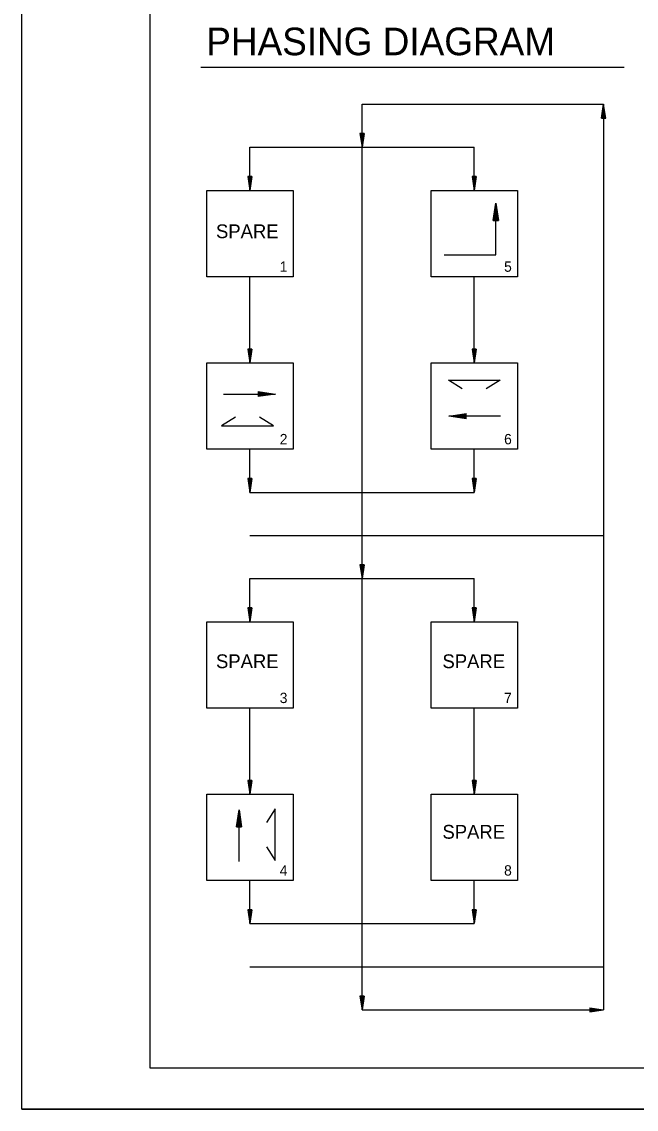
# Model space of a CAD drawing. Extents: x 1280742 to 1281742, y 1892348 to 1892988.
# Drawn here: x 1280741.9 to 1280919.9, y 1892348 to 1892663.2 of the extents above; entities that cross this region are included whole.
import ezdxf

# ---------------------------------------------------------------- set-up
doc = ezdxf.new("R2010")
doc.units = 0
for name, color, linetype in [('R_Border', 7, 'Continuous'), ('R_Draft', 7, 'Continuous'), ('R_No Plot', 7, 'Continuous'), ('T_Drafting', 7, 'Continuous'), ('T_Notes', 7, 'Continuous')]:
    doc.layers.add(name, color=color, linetype=linetype)

msp = doc.modelspace()

# ---------------------------------------------------------------- linework, layer by layer
at = {"layer": 'R_Border'}
for p, q in [((1280779.11, 1892359.96), (1280779.11, 1892976.34)), ((1280779.11, 1892359.96), (1280779.11, 1892575.44)), ((1281154.16, 1892359.96), (1280779.11, 1892359.96)), ((1280779.11, 1892359.96), (1280779.11, 1892359.96)), ((1281727.65, 1892359.96), (1280779.11, 1892359.96))]:
    msp.add_line(p, q, dxfattribs=at)
at = {"layer": 'R_Draft'}
for p, q in [((1280909.87, 1892635.3), (1280910.47, 1892639.3)), ((1280909.97, 1892635.3), (1280910.47, 1892638.64)), ((1280910.07, 1892635.3), (1280910.47, 1892637.95)), ((1280910.17, 1892635.3), (1280910.47, 1892637.28)), ((1280911.07, 1892635.3), (1280910.47, 1892639.3)), ((1280910.97, 1892635.3), (1280910.47, 1892638.64)), ((1280910.87, 1892635.3), (1280910.47, 1892637.95)), ((1280910.77, 1892635.3), (1280910.47, 1892637.28)), ((1280909.87, 1892635.3), (1280911.07, 1892635.3)), ((1280910.28, 1892635.3), (1280910.47, 1892636.6)), ((1280910.38, 1892635.3), (1280910.47, 1892635.94)), ((1280910.67, 1892635.3), (1280910.47, 1892636.6)), ((1280910.56, 1892635.3), (1280910.47, 1892635.94)), ((1280839.87, 1892630.8), (1280840.47, 1892626.8)), ((1280841.07, 1892630.8), (1280839.87, 1892630.8)), ((1280839.97, 1892630.8), (1280840.47, 1892627.47)), ((1280840.07, 1892630.8), (1280840.47, 1892628.16)), ((1280840.17, 1892630.8), (1280840.47, 1892628.83)), ((1280840.27, 1892630.8), (1280840.47, 1892629.5)), ((1280840.38, 1892630.8), (1280840.47, 1892630.17)), ((1280841.07, 1892630.8), (1280840.47, 1892626.8)), ((1280840.66, 1892630.8), (1280840.47, 1892629.5)), ((1280840.87, 1892630.8), (1280840.47, 1892628.16)), ((1280840.97, 1892630.8), (1280840.47, 1892627.47)), ((1280840.77, 1892630.8), (1280840.47, 1892628.83)), ((1280840.56, 1892630.8), (1280840.47, 1892630.17)), ((1280807.37, 1892618.3), (1280807.97, 1892614.3)), ((1280808.57, 1892618.3), (1280807.37, 1892618.3)), ((1280807.47, 1892618.3), (1280807.97, 1892614.97)), ((1280807.57, 1892618.3), (1280807.97, 1892615.66)), ((1280807.67, 1892618.3), (1280807.97, 1892616.33)), ((1280807.77, 1892618.3), (1280807.97, 1892617)), ((1280807.88, 1892618.3), (1280807.97, 1892617.67)), ((1280808.57, 1892618.3), (1280807.97, 1892614.3)), ((1280808.16, 1892618.3), (1280807.97, 1892617)), ((1280808.37, 1892618.3), (1280807.97, 1892615.66)), ((1280808.47, 1892618.3), (1280807.97, 1892614.97)), ((1280808.27, 1892618.3), (1280807.97, 1892616.33)), ((1280808.06, 1892618.3), (1280807.97, 1892617.67)), ((1280872.37, 1892618.3), (1280872.97, 1892614.3)), ((1280873.57, 1892618.3), (1280872.37, 1892618.3)), ((1280872.47, 1892618.3), (1280872.97, 1892614.97)), ((1280872.57, 1892618.3), (1280872.97, 1892615.66)), ((1280872.67, 1892618.3), (1280872.97, 1892616.33)), ((1280872.77, 1892618.3), (1280872.97, 1892617)), ((1280872.88, 1892618.3), (1280872.97, 1892617.67)), ((1280873.57, 1892618.3), (1280872.97, 1892614.3)), ((1280873.16, 1892618.3), (1280872.97, 1892617)), ((1280873.37, 1892618.3), (1280872.97, 1892615.66)), ((1280873.47, 1892618.3), (1280872.97, 1892614.97)), ((1280873.27, 1892618.3), (1280872.97, 1892616.33)), ((1280873.06, 1892618.3), (1280872.97, 1892617.67)), ((1280807.37, 1892568.3), (1280807.97, 1892564.3)), ((1280808.57, 1892568.3), (1280807.37, 1892568.3)), ((1280807.47, 1892568.3), (1280807.97, 1892564.97)), ((1280807.57, 1892568.3), (1280807.97, 1892565.66)), ((1280807.67, 1892568.3), (1280807.97, 1892566.33)), ((1280807.77, 1892568.3), (1280807.97, 1892567)), ((1280807.88, 1892568.3), (1280807.97, 1892567.67)), ((1280808.57, 1892568.3), (1280807.97, 1892564.3)), ((1280808.16, 1892568.3), (1280807.97, 1892567)), ((1280808.37, 1892568.3), (1280807.97, 1892565.66)), ((1280808.47, 1892568.3), (1280807.97, 1892564.97)), ((1280808.27, 1892568.3), (1280807.97, 1892566.33)), ((1280808.06, 1892568.3), (1280807.97, 1892567.67)), ((1280872.37, 1892568.3), (1280872.97, 1892564.3)), ((1280873.57, 1892568.3), (1280872.37, 1892568.3)), ((1280872.47, 1892568.3), (1280872.97, 1892564.97)), ((1280872.57, 1892568.3), (1280872.97, 1892565.66)), ((1280872.67, 1892568.3), (1280872.97, 1892566.33)), ((1280872.77, 1892568.3), (1280872.97, 1892567)), ((1280872.88, 1892568.3), (1280872.97, 1892567.67)), ((1280873.57, 1892568.3), (1280872.97, 1892564.3)), ((1280873.16, 1892568.3), (1280872.97, 1892567)), ((1280873.37, 1892568.3), (1280872.97, 1892565.66)), ((1280873.47, 1892568.3), (1280872.97, 1892564.97)), ((1280873.27, 1892568.3), (1280872.97, 1892566.33)), ((1280873.06, 1892568.3), (1280872.97, 1892567.67)), ((1280807.37, 1892530.8), (1280807.97, 1892526.8)), ((1280808.57, 1892530.8), (1280807.37, 1892530.8)), ((1280807.47, 1892530.8), (1280807.97, 1892527.47)), ((1280807.57, 1892530.8), (1280807.97, 1892528.16)), ((1280807.67, 1892530.8), (1280807.97, 1892528.83)), ((1280807.77, 1892530.8), (1280807.97, 1892529.5)), ((1280807.88, 1892530.8), (1280807.97, 1892530.17)), ((1280808.57, 1892530.8), (1280807.97, 1892526.8)), ((1280808.16, 1892530.8), (1280807.97, 1892529.5)), ((1280808.37, 1892530.8), (1280807.97, 1892528.16)), ((1280808.47, 1892530.8), (1280807.97, 1892527.47)), ((1280808.27, 1892530.8), (1280807.97, 1892528.83)), ((1280808.06, 1892530.8), (1280807.97, 1892530.17)), ((1280872.37, 1892530.8), (1280872.97, 1892526.8)), ((1280873.57, 1892530.8), (1280872.37, 1892530.8)), ((1280872.47, 1892530.8), (1280872.97, 1892527.47)), ((1280872.57, 1892530.8), (1280872.97, 1892528.16)), ((1280872.67, 1892530.8), (1280872.97, 1892528.83)), ((1280872.77, 1892530.8), (1280872.97, 1892529.5)), ((1280872.88, 1892530.8), (1280872.97, 1892530.17)), ((1280873.57, 1892530.8), (1280872.97, 1892526.8)), ((1280873.16, 1892530.8), (1280872.97, 1892529.5)), ((1280873.37, 1892530.8), (1280872.97, 1892528.16)), ((1280873.47, 1892530.8), (1280872.97, 1892527.47)), ((1280873.27, 1892530.8), (1280872.97, 1892528.83)), ((1280873.06, 1892530.8), (1280872.97, 1892530.17)), ((1280839.87, 1892505.8), (1280840.47, 1892501.8)), ((1280841.07, 1892505.8), (1280839.87, 1892505.8)), ((1280839.97, 1892505.8), (1280840.47, 1892502.47)), ((1280840.07, 1892505.8), (1280840.47, 1892503.16)), ((1280840.17, 1892505.8), (1280840.47, 1892503.83)), ((1280840.27, 1892505.8), (1280840.47, 1892504.5)), ((1280840.38, 1892505.8), (1280840.47, 1892505.17)), ((1280841.07, 1892505.8), (1280840.47, 1892501.8)), ((1280840.66, 1892505.8), (1280840.47, 1892504.5)), ((1280840.87, 1892505.8), (1280840.47, 1892503.16)), ((1280840.97, 1892505.8), (1280840.47, 1892502.47)), ((1280840.77, 1892505.8), (1280840.47, 1892503.83)), ((1280840.56, 1892505.8), (1280840.47, 1892505.17)), ((1280807.37, 1892493.3), (1280807.97, 1892489.3)), ((1280808.57, 1892493.3), (1280807.37, 1892493.3)), ((1280807.47, 1892493.3), (1280807.97, 1892489.97)), ((1280807.57, 1892493.3), (1280807.97, 1892490.66)), ((1280807.67, 1892493.3), (1280807.97, 1892491.33)), ((1280807.77, 1892493.3), (1280807.97, 1892492)), ((1280807.88, 1892493.3), (1280807.97, 1892492.67)), ((1280808.57, 1892493.3), (1280807.97, 1892489.3)), ((1280808.16, 1892493.3), (1280807.97, 1892492)), ((1280808.37, 1892493.3), (1280807.97, 1892490.66)), ((1280808.47, 1892493.3), (1280807.97, 1892489.97)), ((1280808.27, 1892493.3), (1280807.97, 1892491.33)), ((1280808.06, 1892493.3), (1280807.97, 1892492.67)), ((1280872.37, 1892493.3), (1280872.97, 1892489.3)), ((1280873.57, 1892493.3), (1280872.37, 1892493.3)), ((1280872.47, 1892493.3), (1280872.97, 1892489.97)), ((1280872.57, 1892493.3), (1280872.97, 1892490.66)), ((1280872.67, 1892493.3), (1280872.97, 1892491.33)), ((1280872.77, 1892493.3), (1280872.97, 1892492)), ((1280872.88, 1892493.3), (1280872.97, 1892492.67)), ((1280873.57, 1892493.3), (1280872.97, 1892489.3)), ((1280873.16, 1892493.3), (1280872.97, 1892492)), ((1280873.37, 1892493.3), (1280872.97, 1892490.66)), ((1280873.47, 1892493.3), (1280872.97, 1892489.97)), ((1280873.27, 1892493.3), (1280872.97, 1892491.33)), ((1280873.06, 1892493.3), (1280872.97, 1892492.67)), ((1280807.37, 1892443.3), (1280807.97, 1892439.3)), ((1280808.57, 1892443.3), (1280807.37, 1892443.3)), ((1280807.47, 1892443.3), (1280807.97, 1892439.97)), ((1280807.57, 1892443.3), (1280807.97, 1892440.66)), ((1280807.67, 1892443.3), (1280807.97, 1892441.33)), ((1280807.77, 1892443.3), (1280807.97, 1892442)), ((1280807.88, 1892443.3), (1280807.97, 1892442.67)), ((1280808.57, 1892443.3), (1280807.97, 1892439.3)), ((1280808.16, 1892443.3), (1280807.97, 1892442)), ((1280808.37, 1892443.3), (1280807.97, 1892440.66)), ((1280808.47, 1892443.3), (1280807.97, 1892439.97)), ((1280808.27, 1892443.3), (1280807.97, 1892441.33)), ((1280808.06, 1892443.3), (1280807.97, 1892442.67)), ((1280872.37, 1892443.3), (1280872.97, 1892439.3)), ((1280873.57, 1892443.3), (1280872.37, 1892443.3)), ((1280872.47, 1892443.3), (1280872.97, 1892439.97)), ((1280872.57, 1892443.3), (1280872.97, 1892440.66)), ((1280872.67, 1892443.3), (1280872.97, 1892441.33)), ((1280872.77, 1892443.3), (1280872.97, 1892442)), ((1280872.88, 1892443.3), (1280872.97, 1892442.67)), ((1280873.57, 1892443.3), (1280872.97, 1892439.3)), ((1280873.16, 1892443.3), (1280872.97, 1892442)), ((1280873.37, 1892443.3), (1280872.97, 1892440.66)), ((1280873.47, 1892443.3), (1280872.97, 1892439.97)), ((1280873.27, 1892443.3), (1280872.97, 1892441.33)), ((1280873.06, 1892443.3), (1280872.97, 1892442.67)), ((1280807.37, 1892405.8), (1280807.97, 1892401.8)), ((1280808.57, 1892405.8), (1280807.37, 1892405.8)), ((1280807.47, 1892405.8), (1280807.97, 1892402.47)), ((1280807.57, 1892405.8), (1280807.97, 1892403.16)), ((1280807.67, 1892405.8), (1280807.97, 1892403.83)), ((1280807.77, 1892405.8), (1280807.97, 1892404.5)), ((1280807.88, 1892405.8), (1280807.97, 1892405.17)), ((1280808.57, 1892405.8), (1280807.97, 1892401.8)), ((1280808.16, 1892405.8), (1280807.97, 1892404.5)), ((1280808.37, 1892405.8), (1280807.97, 1892403.16)), ((1280808.47, 1892405.8), (1280807.97, 1892402.47)), ((1280808.27, 1892405.8), (1280807.97, 1892403.83)), ((1280808.06, 1892405.8), (1280807.97, 1892405.17)), ((1280872.37, 1892405.8), (1280872.97, 1892401.8)), ((1280873.57, 1892405.8), (1280872.37, 1892405.8)), ((1280872.47, 1892405.8), (1280872.97, 1892402.47)), ((1280872.57, 1892405.8), (1280872.97, 1892403.16)), ((1280872.67, 1892405.8), (1280872.97, 1892403.83)), ((1280872.77, 1892405.8), (1280872.97, 1892404.5)), ((1280872.88, 1892405.8), (1280872.97, 1892405.17)), ((1280873.57, 1892405.8), (1280872.97, 1892401.8)), ((1280873.16, 1892405.8), (1280872.97, 1892404.5)), ((1280873.37, 1892405.8), (1280872.97, 1892403.16)), ((1280873.47, 1892405.8), (1280872.97, 1892402.47)), ((1280873.27, 1892405.8), (1280872.97, 1892403.83)), ((1280873.06, 1892405.8), (1280872.97, 1892405.17)), ((1280839.87, 1892380.8), (1280840.47, 1892376.8)), ((1280841.07, 1892380.8), (1280839.87, 1892380.8)), ((1280839.97, 1892380.8), (1280840.47, 1892377.47)), ((1280840.07, 1892380.8), (1280840.47, 1892378.16)), ((1280840.17, 1892380.8), (1280840.47, 1892378.83)), ((1280840.27, 1892380.8), (1280840.47, 1892379.5)), ((1280840.38, 1892380.8), (1280840.47, 1892380.17)), ((1280841.07, 1892380.8), (1280840.47, 1892376.8)), ((1280840.66, 1892380.8), (1280840.47, 1892379.5)), ((1280840.87, 1892380.8), (1280840.47, 1892378.16)), ((1280840.97, 1892380.8), (1280840.47, 1892377.47)), ((1280840.77, 1892380.8), (1280840.47, 1892378.83)), ((1280840.56, 1892380.8), (1280840.47, 1892380.17)), ((1280906.47, 1892377.4), (1280910.47, 1892376.8)), ((1280906.47, 1892377.4), (1280906.47, 1892376.2)), ((1280906.47, 1892377.3), (1280909.8, 1892376.8)), ((1280906.47, 1892377.2), (1280909.11, 1892376.8)), ((1280906.47, 1892377.1), (1280908.45, 1892376.8)), ((1280906.47, 1892377), (1280907.77, 1892376.8)), ((1280906.47, 1892376.9), (1280907.1, 1892376.8)), ((1280906.47, 1892376.2), (1280910.47, 1892376.8)), ((1280906.47, 1892376.61), (1280907.77, 1892376.8)), ((1280906.47, 1892376.41), (1280909.11, 1892376.8)), ((1280906.47, 1892376.3), (1280909.8, 1892376.8)), ((1280906.47, 1892376.51), (1280908.45, 1892376.8)), ((1280906.47, 1892376.71), (1280907.1, 1892376.8))]:
    msp.add_line(p, q, dxfattribs=at)
at = {"layer": 'R_No Plot'}
msp.add_line((1280741.9, 1892348.02), (1281741.9, 1892348.02), dxfattribs=at)
msp.add_lwpolyline([(1280741.88, 1892988.02), (1281741.9, 1892988.02), (1281741.9, 1892348.01), (1280741.88, 1892348.01)], close=True, dxfattribs=at)
at = {"layer": 'T_Drafting'}
for p, q in [((1280840.47, 1892376.8), (1280840.47, 1892639.3)), ((1280840.47, 1892639.3), (1280910.47, 1892639.3)), ((1280910.47, 1892639.3), (1280910.47, 1892376.8)), ((1280807.97, 1892614.3), (1280807.97, 1892626.8)), ((1280807.97, 1892626.8), (1280872.97, 1892626.8)), ((1280872.97, 1892614.3), (1280872.97, 1892626.8)), ((1280878.47, 1892605.61), (1280879.22, 1892610.61)), ((1280879.22, 1892609.78), (1280878.6, 1892605.61)), ((1280878.73, 1892605.61), (1280879.22, 1892608.92)), ((1280879.22, 1892595.61), (1280879.22, 1892610.61)), ((1280879.22, 1892610.61), (1280879.97, 1892605.61)), ((1280879.85, 1892605.61), (1280879.22, 1892609.78)), ((1280879.22, 1892608.92), (1280879.72, 1892605.61)), ((1280878.47, 1892605.61), (1280879.97, 1892605.61)), ((1280879.22, 1892608.08), (1280878.85, 1892605.61)), ((1280878.98, 1892605.61), (1280879.22, 1892607.24)), ((1280879.22, 1892606.4), (1280879.11, 1892605.61)), ((1280879.6, 1892605.61), (1280879.22, 1892608.08)), ((1280879.22, 1892607.24), (1280879.47, 1892605.61)), ((1280879.34, 1892605.61), (1280879.22, 1892606.4)), ((1280864.22, 1892595.61), (1280879.22, 1892595.61)), ((1280807.97, 1892564.3), (1280807.97, 1892589.3)), ((1280872.97, 1892564.3), (1280872.97, 1892589.3)), ((1280800.37, 1892555.29), (1280815.37, 1892555.29)), ((1280810.37, 1892556.04), (1280815.37, 1892555.29)), ((1280810.37, 1892556.04), (1280810.37, 1892554.54)), ((1280814.53, 1892555.29), (1280810.37, 1892555.91)), ((1280810.37, 1892555.78), (1280813.67, 1892555.29)), ((1280812.84, 1892555.29), (1280810.37, 1892555.66)), ((1280810.37, 1892555.53), (1280811.99, 1892555.29)), ((1280811.16, 1892555.29), (1280810.37, 1892555.4)), ((1280815.37, 1892555.29), (1280810.37, 1892554.54)), ((1280810.37, 1892554.66), (1280814.53, 1892555.29)), ((1280813.67, 1892555.29), (1280810.37, 1892554.79)), ((1280810.37, 1892554.91), (1280812.84, 1892555.29)), ((1280811.99, 1892555.29), (1280810.37, 1892555.04)), ((1280810.37, 1892555.17), (1280811.16, 1892555.29)), ((1280865.61, 1892548.9), (1280870.61, 1892549.65)), ((1280880.61, 1892548.9), (1280865.61, 1892548.9)), ((1280870.61, 1892548.15), (1280865.61, 1892548.9)), ((1280870.61, 1892549.52), (1280866.44, 1892548.9)), ((1280866.44, 1892548.9), (1280870.61, 1892548.27)), ((1280867.3, 1892548.9), (1280870.61, 1892549.4)), ((1280870.61, 1892548.4), (1280867.3, 1892548.9)), ((1280870.61, 1892549.27), (1280868.13, 1892548.9)), ((1280868.13, 1892548.9), (1280870.61, 1892548.53)), ((1280868.98, 1892548.9), (1280870.61, 1892549.14)), ((1280870.61, 1892548.66), (1280868.98, 1892548.9)), ((1280870.61, 1892549.02), (1280869.82, 1892548.9)), ((1280869.82, 1892548.9), (1280870.61, 1892548.78)), ((1280870.61, 1892548.15), (1280870.61, 1892549.65)), ((1280807.97, 1892526.8), (1280807.97, 1892539.3)), ((1280872.97, 1892526.8), (1280872.97, 1892539.3)), ((1280807.97, 1892526.8), (1280872.97, 1892526.8)), ((1280807.97, 1892514.3), (1280910.47, 1892514.3)), ((1280807.97, 1892501.8), (1280872.97, 1892501.8)), ((1280807.97, 1892489.3), (1280807.97, 1892501.8)), ((1280872.97, 1892489.3), (1280872.97, 1892501.8)), ((1280807.97, 1892439.3), (1280807.97, 1892464.3)), ((1280872.97, 1892439.3), (1280872.97, 1892464.3)), ((1280804.09, 1892429.82), (1280804.84, 1892434.82)), ((1280804.84, 1892433.98), (1280804.22, 1892429.82)), ((1280804.34, 1892429.82), (1280804.84, 1892433.12)), ((1280804.84, 1892432.29), (1280804.47, 1892429.82)), ((1280804.84, 1892419.82), (1280804.84, 1892434.82)), ((1280804.84, 1892434.82), (1280805.59, 1892429.82)), ((1280805.47, 1892429.82), (1280804.84, 1892433.98)), ((1280804.84, 1892433.12), (1280805.34, 1892429.82)), ((1280805.21, 1892429.82), (1280804.84, 1892432.29)), ((1280804.09, 1892429.82), (1280805.59, 1892429.82)), ((1280804.6, 1892429.82), (1280804.84, 1892431.44)), ((1280804.84, 1892430.61), (1280804.72, 1892429.82)), ((1280804.84, 1892431.44), (1280805.09, 1892429.82)), ((1280804.96, 1892429.82), (1280804.84, 1892430.61)), ((1280807.97, 1892401.8), (1280807.97, 1892414.3)), ((1280872.97, 1892401.8), (1280872.97, 1892414.3)), ((1280807.97, 1892401.8), (1280872.97, 1892401.8)), ((1280807.97, 1892389.3), (1280910.47, 1892389.3)), ((1280840.47, 1892376.8), (1280910.47, 1892376.8))]:
    msp.add_line(p, q, dxfattribs=at)
for points in [[(1280795.47, 1892614.3), (1280820.47, 1892614.3), (1280820.47, 1892589.3), (1280795.47, 1892589.3)], [(1280860.47, 1892614.3), (1280885.47, 1892614.3), (1280885.47, 1892589.3), (1280860.47, 1892589.3)], [(1280795.47, 1892564.3), (1280820.47, 1892564.3), (1280820.47, 1892539.3), (1280795.47, 1892539.3)], [(1280860.47, 1892564.3), (1280885.47, 1892564.3), (1280885.47, 1892539.3), (1280860.47, 1892539.3)], [(1280795.47, 1892489.3), (1280820.47, 1892489.3), (1280820.47, 1892464.3), (1280795.47, 1892464.3)], [(1280860.47, 1892489.3), (1280885.47, 1892489.3), (1280885.47, 1892464.3), (1280860.47, 1892464.3)], [(1280795.47, 1892439.3), (1280820.47, 1892439.3), (1280820.47, 1892414.3), (1280795.47, 1892414.3)], [(1280860.47, 1892439.3), (1280885.47, 1892439.3), (1280885.47, 1892414.3), (1280860.47, 1892414.3)]]:
    msp.add_lwpolyline(points, close=True, dxfattribs=at)
for points in [[(1280869.48, 1892556.8), (1280865.48, 1892559.3), (1280880.48, 1892559.3), (1280876.48, 1892556.8)], [(1280803.8, 1892548.55), (1280799.8, 1892546.05), (1280814.8, 1892546.05), (1280810.8, 1892548.55)], [(1280812.8, 1892424.07), (1280815.3, 1892420.07), (1280815.3, 1892435.07), (1280812.8, 1892431.07)]]:
    msp.add_lwpolyline(points, dxfattribs=at)
at = {"layer": 'T_Notes'}
msp.add_line((1280793.74, 1892650.02), (1280916.39, 1892650.02), dxfattribs=at)

# ---------------------------------------------------------------- texts
at = {"layer": 'T_Drafting'}
for p in [(1280798.16, 1892600.47), (1280798.16, 1892475.85), (1280863.77, 1892475.85), (1280863.77, 1892426.42)]:
    msp.add_text('SPARE', height=4, dxfattribs=at).set_placement(p)
at = {"layer": 'T_Notes'}
for s, height, p in [('PHASING DIAGRAM', 8, (1280795.34, 1892653.49)), ('1', 3, (1280816.63, 1892590.73)), ('5', 3, (1280881.63, 1892590.73)), ('2', 3, (1280816.63, 1892540.73)), ('6', 3, (1280881.63, 1892540.73)), ('3', 3, (1280816.63, 1892465.73)), ('7', 3, (1280881.63, 1892465.73)), ('4', 3, (1280816.63, 1892415.73)), ('8', 3, (1280881.63, 1892415.73))]:
    msp.add_text(s, height=height, dxfattribs=at).set_placement(p)

doc.saveas('drawing.dxf')
